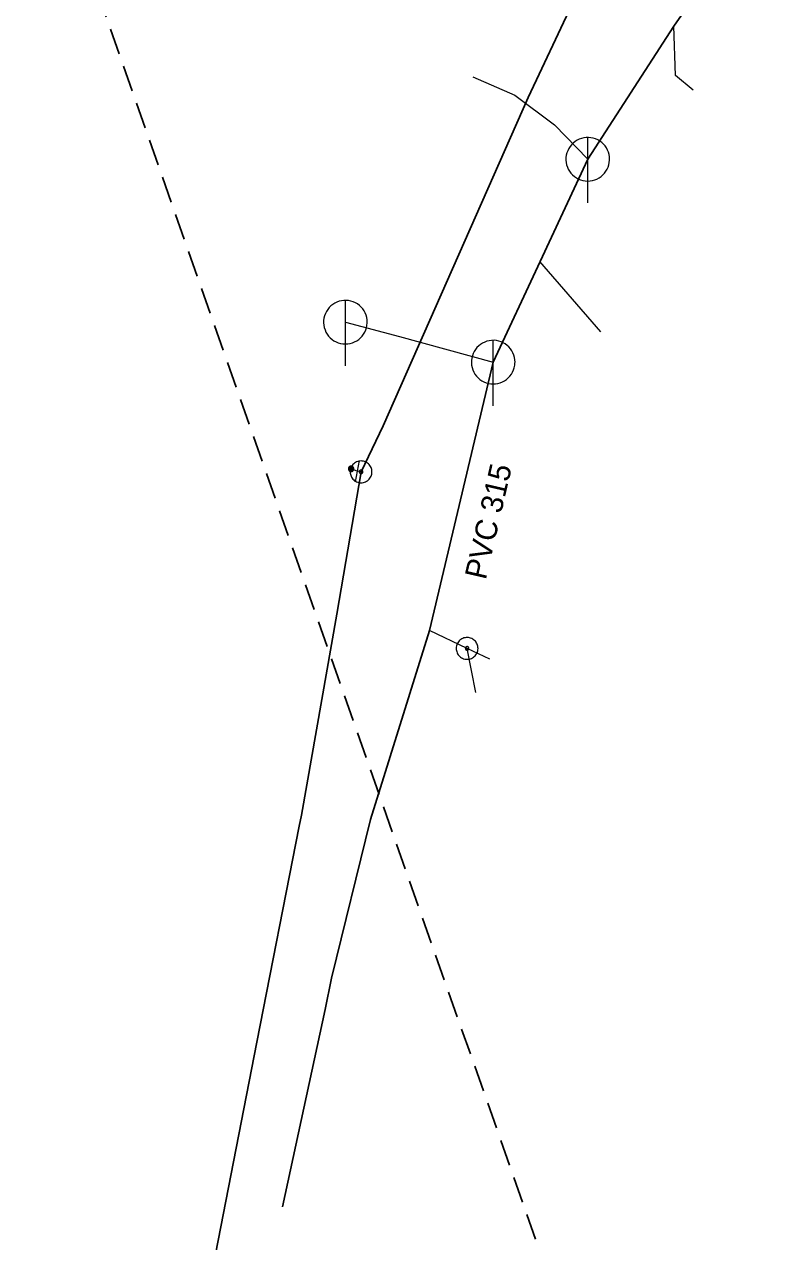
# Model space of a CAD drawing. Extents: x -659250 to -657316, y -997555 to -993684.
# Drawn here: x -658648.7 to -658614.9, y -995254.3 to -995198.5 of the extents above; entities that cross this region are included whole.
import ezdxf

# ---------------------------------------------------------------- set-up
doc = ezdxf.new("R2010")
doc.units = 0
doc.header["$LTSCALE"] = 0.4
doc.linetypes.add('MEDIUM_DASHED', pattern=[4.5, 3, -1.5])
doc.layers.add('1', color=7, linetype='Continuous')
for name, color, linetype, lineweight in [('11', 7, 'Continuous', 13), ('14', 7, 'Continuous', 25), ('17', 7, 'Continuous', 25), ('22', 7, 'Continuous', 13), ('31', 7, 'Continuous', 13), ('34', 7, 'Continuous', 13), ('47', 7, 'Continuous', 13), ('63', 7, 'MEDIUM_DASHED', 25), ('9', 7, 'Continuous', 13)]:
    doc.layers.add(name, color=color, linetype=linetype, lineweight=lineweight)

msp = doc.modelspace()

# ---------------------------------------------------------------- linework, layer by layer
at = {"layer": '11'}
for p, q in [((-658622.32, -995212.59), (-658625.108, -995209.363)), ((-658628.048, -995229.127), (-658628.449, -995227.099))]:
    msp.add_line(p, q, dxfattribs=at)
for points in [[(-658618.088, -995201.496), (-658618.901, -995200.835), (-658618.978, -995198.574)], [(-658628.193, -995200.899), (-658626.257, -995201.725), (-658624.442, -995203.087), (-658622.92, -995204.672)], [(-658634.03, -995212.14), (-658631.55, -995212.8), (-658627.253, -995213.972)], [(-658627.409, -995227.592), (-658628.449, -995227.099), (-658630.18, -995226.28)]]:
    msp.add_lwpolyline(points, dxfattribs=at)
at = {"layer": '14', "lineweight": 13}
for p, q in [((-658633.491, -995218.968), (-658633.767, -995218.864)), ((-658633.311, -995219.004), (-658633.491, -995218.968))]:
    msp.add_line(p, q, dxfattribs=at)
at = {"layer": '14'}
for points in [[(-658622.92, -995204.671), (-658618.978, -995198.574), (-658618.294, -995197.598), (-658616.42, -995194.739)], [(-658627.252, -995213.971), (-658625.107, -995209.363), (-658622.92, -995204.671)], [(-658636.91, -995252.71), (-658634.963, -995243.658), (-658634.67, -995242.219), (-658632.879, -995234.949), (-658630.18, -995226.28), (-658627.252, -995213.971)]]:
    msp.add_lwpolyline(points, dxfattribs=at)
at = {"layer": '17'}
for points in [[(-658633.311, -995219.004), (-658632.3, -995216.89), (-658625.646, -995201.835), (-658623.653, -995197.583), (-658619.796, -995192.896), (-658617.175, -995190.239), (-658616.274, -995189.232), (-658602.428, -995175.557), (-658599.375, -995174.746), (-658589.094, -995179.075), (-658583.371, -995184.746)], [(-658633.311, -995219.004), (-658634.417, -995225.526), (-658636.041, -995234.75), (-658636.149, -995235.243), (-658638.083, -995245.153), (-658640.809, -995259.105), (-658641.458, -995262.408), (-658643.489, -995272.677), (-658644.151, -995277.947), (-658644.223, -995278.522), (-658646.28, -995297.989), (-658642.87, -995311.59)]]:
    msp.add_lwpolyline(points, dxfattribs=at)
at = {"layer": '22'}
for p, q in [((-658622.92, -995206.671), (-658622.919, -995203.671)), ((-658634.03, -995214.14), (-658634.029, -995211.14)), ((-658627.253, -995215.972), (-658627.252, -995212.972))]:
    msp.add_line(p, q, dxfattribs=at)
for points in [[(-658621.92, -995204.671), (-658621.925, -995204.562), (-658621.943, -995204.454), (-658621.973, -995204.348), (-658622.013, -995204.247), (-658622.065, -995204.15), (-658622.127, -995204.06), (-658622.199, -995203.977), (-658622.279, -995203.903), (-658622.367, -995203.837), (-658622.461, -995203.782), (-658622.561, -995203.737), (-658622.666, -995203.704), (-658622.773, -995203.682), (-658622.882, -995203.672), (-658622.992, -995203.674), (-658623.1, -995203.688), (-658623.207, -995203.713), (-658623.31, -995203.75), (-658623.408, -995203.799), (-658623.5, -995203.857), (-658623.586, -995203.926), (-658623.663, -995204.003), (-658623.732, -995204.089), (-658623.791, -995204.181), (-658623.839, -995204.279), (-658623.876, -995204.382), (-658623.902, -995204.489), (-658623.916, -995204.597), (-658623.919, -995204.707), (-658623.909, -995204.816), (-658623.888, -995204.923), (-658623.854, -995205.027), (-658623.81, -995205.127), (-658623.755, -995205.222), (-658623.689, -995205.31), (-658623.615, -995205.39), (-658623.532, -995205.462), (-658623.442, -995205.524), (-658623.346, -995205.576), (-658623.244, -995205.617), (-658623.139, -995205.647), (-658623.031, -995205.665), (-658622.921, -995205.671), (-658622.812, -995205.665), (-658622.704, -995205.647), (-658622.599, -995205.618), (-658622.497, -995205.577), (-658622.4, -995205.525), (-658622.31, -995205.463), (-658622.227, -995205.392), (-658622.152, -995205.312), (-658622.087, -995205.224), (-658622.031, -995205.13), (-658621.987, -995205.03), (-658621.953, -995204.926), (-658621.931, -995204.818), (-658621.921, -995204.709)], [(-658633.03, -995212.14), (-658633.035, -995212.031), (-658633.053, -995211.923), (-658633.083, -995211.817), (-658633.123, -995211.716), (-658633.175, -995211.619), (-658633.237, -995211.529), (-658633.309, -995211.446), (-658633.389, -995211.372), (-658633.477, -995211.306), (-658633.571, -995211.251), (-658633.671, -995211.206), (-658633.776, -995211.173), (-658633.883, -995211.151), (-658633.992, -995211.141), (-658634.102, -995211.143), (-658634.21, -995211.157), (-658634.317, -995211.182), (-658634.42, -995211.219), (-658634.518, -995211.268), (-658634.61, -995211.326), (-658634.696, -995211.395), (-658634.773, -995211.472), (-658634.842, -995211.558), (-658634.901, -995211.65), (-658634.949, -995211.748), (-658634.986, -995211.851), (-658635.012, -995211.958), (-658635.026, -995212.066), (-658635.029, -995212.176), (-658635.019, -995212.285), (-658634.998, -995212.392), (-658634.964, -995212.496), (-658634.92, -995212.596), (-658634.865, -995212.691), (-658634.799, -995212.779), (-658634.725, -995212.859), (-658634.642, -995212.931), (-658634.552, -995212.993), (-658634.456, -995213.045), (-658634.354, -995213.086), (-658634.249, -995213.116), (-658634.141, -995213.134), (-658634.031, -995213.14), (-658633.922, -995213.134), (-658633.814, -995213.116), (-658633.709, -995213.087), (-658633.607, -995213.046), (-658633.51, -995212.994), (-658633.42, -995212.932), (-658633.337, -995212.861), (-658633.262, -995212.781), (-658633.197, -995212.693), (-658633.141, -995212.599), (-658633.097, -995212.499), (-658633.063, -995212.395), (-658633.041, -995212.287), (-658633.031, -995212.178)], [(-658626.253, -995213.972), (-658626.258, -995213.863), (-658626.276, -995213.755), (-658626.306, -995213.649), (-658626.346, -995213.548), (-658626.398, -995213.451), (-658626.46, -995213.361), (-658626.532, -995213.278), (-658626.612, -995213.204), (-658626.7, -995213.138), (-658626.794, -995213.083), (-658626.894, -995213.038), (-658626.999, -995213.005), (-658627.106, -995212.983), (-658627.215, -995212.973), (-658627.325, -995212.975), (-658627.433, -995212.989), (-658627.54, -995213.014), (-658627.643, -995213.051), (-658627.741, -995213.1), (-658627.833, -995213.158), (-658627.919, -995213.227), (-658627.996, -995213.304), (-658628.065, -995213.39), (-658628.124, -995213.482), (-658628.172, -995213.58), (-658628.209, -995213.683), (-658628.235, -995213.79), (-658628.249, -995213.898), (-658628.252, -995214.008), (-658628.242, -995214.117), (-658628.221, -995214.224), (-658628.187, -995214.328), (-658628.143, -995214.428), (-658628.088, -995214.523), (-658628.022, -995214.611), (-658627.948, -995214.691), (-658627.865, -995214.763), (-658627.775, -995214.825), (-658627.679, -995214.877), (-658627.577, -995214.918), (-658627.472, -995214.948), (-658627.364, -995214.966), (-658627.254, -995214.972), (-658627.145, -995214.966), (-658627.037, -995214.948), (-658626.932, -995214.919), (-658626.83, -995214.878), (-658626.733, -995214.826), (-658626.643, -995214.764), (-658626.56, -995214.693), (-658626.485, -995214.613), (-658626.42, -995214.525), (-658626.364, -995214.431), (-658626.32, -995214.331), (-658626.286, -995214.227), (-658626.264, -995214.119), (-658626.254, -995214.01)]]:
    msp.add_lwpolyline(points, close=True, dxfattribs=at)
at = {"layer": '31'}
for points in [[(-658628.351, -995227.589), (-658628.301, -995227.576), (-658628.251, -995227.558), (-658628.205, -995227.534), (-658628.16, -995227.507), (-658628.119, -995227.475), (-658628.082, -995227.438), (-658628.049, -995227.397), (-658628.02, -995227.354), (-658627.995, -995227.308), (-658627.975, -995227.259), (-658627.961, -995227.209), (-658627.953, -995227.157), (-658627.949, -995227.105), (-658627.951, -995227.053), (-658627.958, -995227.001), (-658627.971, -995226.951), (-658627.989, -995226.901), (-658628.013, -995226.854), (-658628.04, -995226.81), (-658628.072, -995226.769), (-658628.109, -995226.732), (-658628.15, -995226.698), (-658628.193, -995226.669), (-658628.239, -995226.644), (-658628.288, -995226.625), (-658628.338, -995226.611), (-658628.39, -995226.602), (-658628.442, -995226.599), (-658628.494, -995226.601), (-658628.546, -995226.608), (-658628.596, -995226.621), (-658628.646, -995226.639), (-658628.693, -995226.662), (-658628.737, -995226.69), (-658628.778, -995226.722), (-658628.816, -995226.758), (-658628.849, -995226.799), (-658628.879, -995226.842), (-658628.903, -995226.889), (-658628.922, -995226.938), (-658628.936, -995226.988), (-658628.946, -995227.039), (-658628.948, -995227.092), (-658628.946, -995227.144), (-658628.939, -995227.196), (-658628.926, -995227.246), (-658628.908, -995227.296), (-658628.885, -995227.342), (-658628.857, -995227.387), (-658628.825, -995227.428), (-658628.789, -995227.466), (-658628.748, -995227.498), (-658628.705, -995227.528), (-658628.658, -995227.552), (-658628.609, -995227.572), (-658628.559, -995227.586), (-658628.508, -995227.595), (-658628.455, -995227.598), (-658628.403, -995227.596)], [(-658628.433, -995227.179), (-658628.424, -995227.177), (-658628.416, -995227.174), (-658628.409, -995227.17), (-658628.402, -995227.166), (-658628.394, -995227.16), (-658628.389, -995227.154), (-658628.383, -995227.148), (-658628.378, -995227.141), (-658628.374, -995227.133), (-658628.371, -995227.125), (-658628.369, -995227.116), (-658628.367, -995227.108), (-658628.367, -995227.1), (-658628.366, -995227.091), (-658628.368, -995227.083), (-658628.37, -995227.074), (-658628.373, -995227.066), (-658628.377, -995227.059), (-658628.381, -995227.052), (-658628.387, -995227.044), (-658628.393, -995227.039), (-658628.399, -995227.033), (-658628.406, -995227.028), (-658628.414, -995227.023), (-658628.422, -995227.021), (-658628.431, -995227.019), (-658628.439, -995227.017), (-658628.447, -995227.017), (-658628.456, -995227.016), (-658628.464, -995227.018), (-658628.473, -995227.02), (-658628.481, -995227.023), (-658628.488, -995227.027), (-658628.495, -995227.031), (-658628.503, -995227.037), (-658628.509, -995227.042), (-658628.514, -995227.049), (-658628.519, -995227.056), (-658628.524, -995227.064), (-658628.526, -995227.072), (-658628.528, -995227.081), (-658628.53, -995227.089), (-658628.53, -995227.097), (-658628.531, -995227.106), (-658628.529, -995227.114), (-658628.527, -995227.123), (-658628.524, -995227.131), (-658628.52, -995227.138), (-658628.516, -995227.145), (-658628.51, -995227.153), (-658628.505, -995227.159), (-658628.498, -995227.164), (-658628.491, -995227.169), (-658628.483, -995227.173), (-658628.475, -995227.176), (-658628.466, -995227.178), (-658628.458, -995227.18), (-658628.45, -995227.18), (-658628.441, -995227.181)]]:
    msp.add_lwpolyline(points, close=True, dxfattribs=at)
at = {"layer": '34'}
msp.add_line((-658633.396, -995218.476), (-658633.586, -995219.458), dxfattribs=at)
at = {"layer": '47'}
for points in [[(-658632.811, -995219.004), (-658632.814, -995218.951), (-658632.822, -995218.899), (-658632.836, -995218.85), (-658632.853, -995218.801), (-658632.878, -995218.754), (-658632.907, -995218.71), (-658632.94, -995218.669), (-658632.977, -995218.632), (-658633.017, -995218.6), (-658633.061, -995218.571), (-658633.108, -995218.546), (-658633.157, -995218.529), (-658633.206, -995218.515), (-658633.259, -995218.507), (-658633.311, -995218.504), (-658633.363, -995218.507), (-658633.415, -995218.515), (-658633.466, -995218.529), (-658633.514, -995218.546), (-658633.561, -995218.571), (-658633.605, -995218.6), (-658633.646, -995218.632), (-658633.683, -995218.669), (-658633.716, -995218.71), (-658633.744, -995218.754), (-658633.768, -995218.801), (-658633.787, -995218.85), (-658633.799, -995218.899), (-658633.808, -995218.951), (-658633.811, -995219.004), (-658633.808, -995219.056), (-658633.799, -995219.108), (-658633.787, -995219.159), (-658633.768, -995219.206), (-658633.744, -995219.254), (-658633.716, -995219.298), (-658633.683, -995219.338), (-658633.646, -995219.375), (-658633.605, -995219.409), (-658633.561, -995219.436), (-658633.514, -995219.461), (-658633.466, -995219.48), (-658633.415, -995219.492), (-658633.363, -995219.5), (-658633.311, -995219.504), (-658633.259, -995219.5), (-658633.206, -995219.492), (-658633.157, -995219.48), (-658633.108, -995219.461), (-658633.061, -995219.436), (-658633.017, -995219.409), (-658632.977, -995219.375), (-658632.94, -995219.338), (-658632.907, -995219.298), (-658632.878, -995219.254), (-658632.853, -995219.206), (-658632.836, -995219.159), (-658632.822, -995219.108), (-658632.814, -995219.056)], [(-658633.228, -995219.004), (-658633.228, -995218.995), (-658633.231, -995218.987), (-658633.233, -995218.978), (-658633.236, -995218.97), (-658633.24, -995218.963), (-658633.245, -995218.956), (-658633.25, -995218.948), (-658633.255, -995218.943), (-658633.263, -995218.938), (-658633.27, -995218.933), (-658633.277, -995218.929), (-658633.286, -995218.926), (-658633.294, -995218.924), (-658633.302, -995218.921), (-658633.311, -995218.921), (-658633.32, -995218.921), (-658633.328, -995218.924), (-658633.336, -995218.926), (-658633.344, -995218.929), (-658633.352, -995218.933), (-658633.358, -995218.938), (-658633.366, -995218.943), (-658633.372, -995218.948), (-658633.378, -995218.956), (-658633.382, -995218.963), (-658633.386, -995218.97), (-658633.389, -995218.978), (-658633.391, -995218.987), (-658633.393, -995218.995), (-658633.393, -995219.004), (-658633.393, -995219.012), (-658633.391, -995219.021), (-658633.389, -995219.029), (-658633.386, -995219.037), (-658633.382, -995219.044), (-658633.378, -995219.051), (-658633.372, -995219.059), (-658633.366, -995219.065), (-658633.358, -995219.071), (-658633.352, -995219.075), (-658633.344, -995219.078), (-658633.336, -995219.081), (-658633.328, -995219.083), (-658633.32, -995219.086), (-658633.311, -995219.086), (-658633.302, -995219.086), (-658633.294, -995219.083), (-658633.286, -995219.081), (-658633.277, -995219.078), (-658633.27, -995219.075), (-658633.263, -995219.071), (-658633.255, -995219.065), (-658633.25, -995219.059), (-658633.245, -995219.051), (-658633.24, -995219.044), (-658633.236, -995219.037), (-658633.233, -995219.029), (-658633.231, -995219.021), (-658633.228, -995219.012)]]:
    msp.add_lwpolyline(points, close=True, dxfattribs=at)
at = {"layer": '63'}
msp.add_lwpolyline([(-659116.685, -993855.266), (-658551.464, -993848.288), (-658551.464, -993848.288), (-657316.352, -997490.822), (-657316.352, -997490.822), (-657839.705, -997490.822), (-657839.705, -997490.822)], close=True, dxfattribs=at)
at = {"layer": '9'}
for points in [[(-658633.893, -995218.864), (-658633.893, -995218.877), (-658633.891, -995218.89), (-658633.888, -995218.903), (-658633.883, -995218.915), (-658633.877, -995218.927), (-658633.87, -995218.938), (-658633.862, -995218.948), (-658633.852, -995218.958), (-658633.842, -995218.966), (-658633.831, -995218.973), (-658633.819, -995218.979), (-658633.807, -995218.984), (-658633.794, -995218.987), (-658633.781, -995218.989), (-658633.768, -995218.991), (-658633.755, -995218.99), (-658633.742, -995218.988), (-658633.729, -995218.985), (-658633.717, -995218.98), (-658633.705, -995218.974), (-658633.694, -995218.967), (-658633.684, -995218.959), (-658633.674, -995218.949), (-658633.666, -995218.939), (-658633.659, -995218.928), (-658633.653, -995218.916), (-658633.648, -995218.904), (-658633.645, -995218.891), (-658633.643, -995218.878), (-658633.641, -995218.865), (-658633.642, -995218.852), (-658633.644, -995218.839), (-658633.647, -995218.826), (-658633.652, -995218.814), (-658633.657, -995218.802), (-658633.665, -995218.791), (-658633.673, -995218.781), (-658633.683, -995218.771), (-658633.693, -995218.763), (-658633.704, -995218.756), (-658633.716, -995218.75), (-658633.728, -995218.745), (-658633.741, -995218.742), (-658633.754, -995218.74), (-658633.767, -995218.739), (-658633.78, -995218.739), (-658633.793, -995218.741), (-658633.806, -995218.744), (-658633.818, -995218.749), (-658633.83, -995218.755), (-658633.841, -995218.762), (-658633.851, -995218.77), (-658633.861, -995218.78), (-658633.869, -995218.79), (-658633.876, -995218.801), (-658633.882, -995218.813), (-658633.887, -995218.825), (-658633.89, -995218.838), (-658633.892, -995218.851)], [(-658633.873, -995218.864), (-658633.874, -995218.875), (-658633.872, -995218.886), (-658633.869, -995218.897), (-658633.865, -995218.907), (-658633.86, -995218.917), (-658633.854, -995218.926), (-658633.847, -995218.935), (-658633.839, -995218.943), (-658633.83, -995218.95), (-658633.821, -995218.956), (-658633.811, -995218.961), (-658633.801, -995218.965), (-658633.79, -995218.968), (-658633.779, -995218.971), (-658633.768, -995218.971), (-658633.757, -995218.971), (-658633.746, -995218.969), (-658633.735, -995218.966), (-658633.725, -995218.962), (-658633.715, -995218.957), (-658633.706, -995218.951), (-658633.697, -995218.944), (-658633.689, -995218.936), (-658633.682, -995218.927), (-658633.676, -995218.918), (-658633.671, -995218.908), (-658633.667, -995218.898), (-658633.664, -995218.887), (-658633.662, -995218.876), (-658633.661, -995218.865), (-658633.661, -995218.854), (-658633.663, -995218.843), (-658633.666, -995218.832), (-658633.67, -995218.822), (-658633.675, -995218.812), (-658633.681, -995218.803), (-658633.688, -995218.794), (-658633.696, -995218.786), (-658633.705, -995218.779), (-658633.714, -995218.773), (-658633.724, -995218.768), (-658633.733, -995218.764), (-658633.745, -995218.761), (-658633.755, -995218.759), (-658633.767, -995218.759), (-658633.778, -995218.758), (-658633.789, -995218.76), (-658633.8, -995218.763), (-658633.809, -995218.767), (-658633.82, -995218.772), (-658633.829, -995218.778), (-658633.838, -995218.785), (-658633.846, -995218.793), (-658633.853, -995218.802), (-658633.858, -995218.811), (-658633.864, -995218.821), (-658633.868, -995218.831), (-658633.871, -995218.842), (-658633.873, -995218.853)], [(-658633.854, -995218.864), (-658633.854, -995218.873), (-658633.853, -995218.882), (-658633.85, -995218.891), (-658633.847, -995218.899), (-658633.843, -995218.907), (-658633.838, -995218.915), (-658633.831, -995218.922), (-658633.826, -995218.928), (-658633.819, -995218.934), (-658633.811, -995218.939), (-658633.803, -995218.943), (-658633.795, -995218.946), (-658633.786, -995218.949), (-658633.777, -995218.95), (-658633.768, -995218.952), (-658633.759, -995218.951), (-658633.75, -995218.95), (-658633.741, -995218.947), (-658633.733, -995218.944), (-658633.725, -995218.94), (-658633.717, -995218.935), (-658633.71, -995218.929), (-658633.704, -995218.923), (-658633.698, -995218.916), (-658633.693, -995218.908), (-658633.689, -995218.9), (-658633.686, -995218.892), (-658633.683, -995218.883), (-658633.682, -995218.874), (-658633.679, -995218.865), (-658633.681, -995218.856), (-658633.682, -995218.847), (-658633.684, -995218.838), (-658633.688, -995218.83), (-658633.692, -995218.822), (-658633.697, -995218.814), (-658633.703, -995218.807), (-658633.709, -995218.801), (-658633.716, -995218.795), (-658633.724, -995218.79), (-658633.732, -995218.786), (-658633.74, -995218.783), (-658633.749, -995218.78), (-658633.758, -995218.779), (-658633.767, -995218.778), (-658633.776, -995218.778), (-658633.785, -995218.779), (-658633.794, -995218.782), (-658633.802, -995218.785), (-658633.809, -995218.789), (-658633.818, -995218.794), (-658633.825, -995218.8), (-658633.831, -995218.806), (-658633.837, -995218.813), (-658633.842, -995218.821), (-658633.846, -995218.829), (-658633.849, -995218.837), (-658633.852, -995218.846), (-658633.853, -995218.855)], [(-658633.834, -995218.864), (-658633.834, -995218.871), (-658633.833, -995218.878), (-658633.831, -995218.885), (-658633.829, -995218.891), (-658633.826, -995218.897), (-658633.822, -995218.903), (-658633.818, -995218.909), (-658633.813, -995218.914), (-658633.807, -995218.918), (-658633.801, -995218.922), (-658633.795, -995218.925), (-658633.789, -995218.928), (-658633.782, -995218.929), (-658633.775, -995218.932), (-658633.768, -995218.932), (-658633.761, -995218.932), (-658633.754, -995218.93), (-658633.747, -995218.929), (-658633.741, -995218.926), (-658633.733, -995218.923), (-658633.729, -995218.919), (-658633.723, -995218.915), (-658633.718, -995218.91), (-658633.714, -995218.904), (-658633.71, -995218.898), (-658633.706, -995218.892), (-658633.704, -995218.886), (-658633.702, -995218.879), (-658633.701, -995218.872), (-658633.7, -995218.865), (-658633.7, -995218.858), (-658633.701, -995218.851), (-658633.703, -995218.844), (-658633.706, -995218.838), (-658633.709, -995218.831), (-658633.713, -995218.826), (-658633.717, -995218.82), (-658633.722, -995218.815), (-658633.728, -995218.811), (-658633.733, -995218.807), (-658633.74, -995218.804), (-658633.746, -995218.801), (-658633.753, -995218.799), (-658633.76, -995218.798), (-658633.767, -995218.798), (-658633.774, -995218.798), (-658633.781, -995218.798), (-658633.788, -995218.8), (-658633.794, -995218.803), (-658633.8, -995218.806), (-658633.806, -995218.81), (-658633.812, -995218.814), (-658633.817, -995218.819), (-658633.821, -995218.825), (-658633.825, -995218.83), (-658633.828, -995218.837), (-658633.831, -995218.843), (-658633.831, -995218.85), (-658633.834, -995218.857)], [(-658633.814, -995218.864), (-658633.814, -995218.869), (-658633.814, -995218.874), (-658633.813, -995218.879), (-658633.811, -995218.883), (-658633.809, -995218.888), (-658633.806, -995218.892), (-658633.803, -995218.895), (-658633.799, -995218.899), (-658633.796, -995218.902), (-658633.792, -995218.905), (-658633.787, -995218.907), (-658633.782, -995218.909), (-658633.778, -995218.91), (-658633.773, -995218.912), (-658633.768, -995218.912), (-658633.763, -995218.912), (-658633.758, -995218.911), (-658633.753, -995218.91), (-658633.749, -995218.908), (-658633.744, -995218.906), (-658633.74, -995218.903), (-658633.736, -995218.9), (-658633.733, -995218.896), (-658633.73, -995218.893), (-658633.727, -995218.889), (-658633.725, -995218.884), (-658633.723, -995218.88), (-658633.722, -995218.875), (-658633.721, -995218.87), (-658633.72, -995218.865), (-658633.72, -995218.86), (-658633.721, -995218.855), (-658633.722, -995218.85), (-658633.724, -995218.846), (-658633.726, -995218.841), (-658633.729, -995218.837), (-658633.732, -995218.833), (-658633.735, -995218.83), (-658633.739, -995218.827), (-658633.743, -995218.824), (-658633.748, -995218.822), (-658633.752, -995218.82), (-658633.757, -995218.819), (-658633.762, -995218.818), (-658633.767, -995218.818), (-658633.772, -995218.818), (-658633.777, -995218.819), (-658633.782, -995218.819), (-658633.786, -995218.821), (-658633.791, -995218.823), (-658633.795, -995218.826), (-658633.798, -995218.829), (-658633.802, -995218.832), (-658633.804, -995218.836), (-658633.808, -995218.84), (-658633.809, -995218.845), (-658633.812, -995218.849), (-658633.813, -995218.854), (-658633.814, -995218.859)], [(-658633.794, -995218.864), (-658633.794, -995218.867), (-658633.795, -995218.87), (-658633.794, -995218.872), (-658633.793, -995218.875), (-658633.792, -995218.878), (-658633.79, -995218.88), (-658633.788, -995218.882), (-658633.786, -995218.884), (-658633.784, -995218.886), (-658633.782, -995218.888), (-658633.779, -995218.89), (-658633.776, -995218.891), (-658633.774, -995218.891), (-658633.771, -995218.892), (-658633.768, -995218.892), (-658633.765, -995218.892), (-658633.762, -995218.892), (-658633.759, -995218.891), (-658633.757, -995218.89), (-658633.754, -995218.889), (-658633.752, -995218.887), (-658633.749, -995218.885), (-658633.747, -995218.883), (-658633.746, -995218.881), (-658633.744, -995218.879), (-658633.743, -995218.876), (-658633.741, -995218.873), (-658633.741, -995218.871), (-658633.74, -995218.868), (-658633.739, -995218.865), (-658633.74, -995218.862), (-658633.74, -995218.859), (-658633.741, -995218.856), (-658633.742, -995218.854), (-658633.743, -995218.851), (-658633.745, -995218.849), (-658633.746, -995218.846), (-658633.748, -995218.844), (-658633.751, -995218.843), (-658633.753, -995218.841), (-658633.755, -995218.84), (-658633.758, -995218.839), (-658633.761, -995218.838), (-658633.764, -995218.838), (-658633.767, -995218.837), (-658633.77, -995218.838), (-658633.773, -995218.837), (-658633.775, -995218.839), (-658633.778, -995218.839), (-658633.781, -995218.84), (-658633.782, -995218.842), (-658633.785, -995218.843), (-658633.787, -995218.845), (-658633.789, -995218.848), (-658633.791, -995218.85), (-658633.792, -995218.853), (-658633.793, -995218.855), (-658633.794, -995218.858), (-658633.794, -995218.861)], [(-658633.775, -995218.864), (-658633.775, -995218.866), (-658633.775, -995218.866), (-658633.774, -995218.866), (-658633.774, -995218.868), (-658633.775, -995218.869), (-658633.773, -995218.869), (-658633.773, -995218.869), (-658633.773, -995218.871), (-658633.773, -995218.871), (-658633.772, -995218.872), (-658633.77, -995218.872), (-658633.77, -995218.872), (-658633.77, -995218.873), (-658633.768, -995218.873), (-658633.768, -995218.873), (-658633.767, -995218.873), (-658633.766, -995218.873), (-658633.766, -995218.872), (-658633.765, -995218.872), (-658633.763, -995218.872), (-658633.763, -995218.871), (-658633.763, -995218.871), (-658633.762, -995218.87), (-658633.762, -995218.87), (-658633.76, -995218.869), (-658633.76, -995218.868), (-658633.759, -995218.867), (-658633.759, -995218.867), (-658633.759, -995218.866), (-658633.759, -995218.865), (-658633.759, -995218.864), (-658633.759, -995218.863), (-658633.759, -995218.863), (-658633.76, -995218.862), (-658633.76, -995218.861), (-658633.761, -995218.86), (-658633.761, -995218.86), (-658633.762, -995218.859), (-658633.762, -995218.859), (-658633.763, -995218.858), (-658633.764, -995218.858), (-658633.765, -995218.857), (-658633.765, -995218.857), (-658633.766, -995218.857), (-658633.767, -995218.857), (-658633.768, -995218.857), (-658633.769, -995218.857), (-658633.769, -995218.857), (-658633.77, -995218.858), (-658633.771, -995218.857), (-658633.772, -995218.859), (-658633.772, -995218.859), (-658633.773, -995218.859), (-658633.773, -995218.859), (-658633.774, -995218.861), (-658633.774, -995218.862), (-658633.774, -995218.863), (-658633.775, -995218.863), (-658633.775, -995218.864)]]:
    msp.add_lwpolyline(points, close=True, dxfattribs=at)

# ---------------------------------------------------------------- texts
at = {"layer": '1'}
msp.add_text('PVC 315 ', height=1, rotation=77, dxfattribs=at).set_placement((-658627.594, -995223.989))

doc.saveas('drawing.dxf')
